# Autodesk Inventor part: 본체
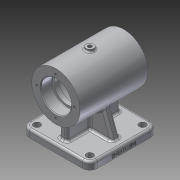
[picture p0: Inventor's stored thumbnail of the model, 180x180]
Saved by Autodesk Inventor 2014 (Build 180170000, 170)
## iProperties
Created: 2019-06
Part Number: 본체
Material: 알루미늄 6061
Document SubType Name: Modeling
Designer: OA55
Density: 2.71 g/cm^3
Appearance: 알루미늄 - 평지
Author: OA55
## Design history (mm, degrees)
sketch "스케치1"
  geometry: C1 r 32 at (0, 0); 1 further point
  constraints: 1 centre point, 1 coincident
  dimensions: "d0" = 64 diameter of C1
extrude "돌출1" new body sketch "스케치1" stored distance "d1" = 90; taper "d2" = 0 deg
node "작업 평면1"
sketch "스케치2"
  geometry: C1 r 25 at (0, 0); 1 further point
  constraints: 1 centre point, 1 coincident
  dimensions: "d3" = 50 diameter of C1
extrude "돌출2" cut sketch "스케치2" stored distance "d4" = 48; taper "d5" = 0 deg
sketch "스케치3"
  geometry: C1 r 32 at (0, 0) reference; C2 r 20 at (0, 0)
  constraints: 1 centre point, 1 coincident
  dimensions: "d6" = 40 diameter of C2
extrude "돌출3" cut sketch "스케치3" distance "d7" = 15; taper "d8" = 0 deg
node "작업 평면2"
sketch "스케치4"
  geometry: C1 r 20 at (0, 0) reference; C2 r 17 at (0, 0)
  constraints: 1 centre point, 1 coincident
  dimensions: "d9" = 34 diameter of C2
extrude "돌출4" cut sketch "스케치4" stored distance "d10" = 15; taper "d11" = 0 deg
sketch "스케치5" dims "d12" = 50
  geometry: L1 (0, 0)-(0, 25); C1 r 32 at (0, 0) reference; 1 further point
  constraints: 2 coincident, 2 end point, 1 vertical, 1 vertical alignment, 2 other
hole "구멍1" sketch "스케치5" at (0, 25) diameter "d13" = 3.242; stored, may be unused: countersink angle "d17" = 90 deg, drill point angle "d19" = 118 deg; dims "d14" = 7, "d15" = 4, "d16" = 2, "d18" = 9
node "작업 평면3"
node "작업 평면4"
sketch "스케치6"
  geometry: C1 r 5 at (0, 0); 1 further point
  constraints: 1 centre point, 1 coincident
  dimensions: "d24" = 10 diameter of C1
extrude "돌출5" join sketch "스케치6" stored distance "d25" = 10; taper "d26" = 0 deg
sketch "스케치7"
  geometry: 2 further points
  constraints: 1 coincident
hole "구멍2" sketch "스케치7" at (0, 0) diameter "d27" = 4.917; stored, may be unused: countersink angle "d31" = 90 deg, drill point angle "d33" = 118 deg; dims "d28" = 10, "d29" = 4, "d30" = 2, "d32" = 20
fillet "모깎기1" dims "d34" = 2
node "작업 평면6"
sketch "스케치8"
  geometry: L1 (0, 0)-(0, 45); L2 (0, 45)-(-45, 45); L3 (-45, 45)-(-45, -45); L4 (-45, -45)-(45, -45); L5 (45, -45)-(45, 45); L6 (45, 45)-(0, 45); 1 further point
  constraints: 12 end point, 3 vertical, 2 horizontal, 1 coincident
  dimensions: "d37" = 45 distance of L1.start L1.end; "d38" = 45 distance of L1.end L2.end; "d39" = 90 distance of L2.end L3.end; "d40" = 90 distance of L3.end L4.end; "d41" = 90 distance of L4.end L5.end
extrude "돌출6" join sketch "스케치8" distance "d42" = 10; taper "d43" = 0 deg
fillet "모깎기2" dims "d44" = 10
sketch "스케치9"
  geometry: C1 r 4.5 at (-35, 35); C2 r 4.5 at (35, 35); C3 r 4.5 at (-35, -35); C4 r 4.5 at (35, -35); A1 r 10 centre (-35, 35) between (-35, 45) and (-45, 35) reference; A2 r 10 centre (-35, -35) between (-45, -35) and (-35, -45) reference; A3 r 10 centre (35, -35) between (35, -45) and (45, -35) reference; A4 r 10 centre (35, 35) between (45, 35) and (35, 45) reference; 1 further point
  constraints: 4 centre point, 4 coincident
  dimensions: "d45" = 9 diameter of C1; "d46" = 9 diameter of C2; "d47" = 9 diameter of C3; "d48" = 9 diameter of C4
fillet "모깎기3" dims "d51" = 3
fillet "모깎기4" dims "d52" = 0.6
sketch "스케치11"
  geometry: L1 (35, -45)-(-35, -45) reference; L2 (45, 35)-(45, -35) reference; L3 (-35, 45)-(35, 45) reference; L4 (0, 0)-(0, 40); L5 (0, 40)-(-26.34, 40); L6 (-40, 26.34)-(-40, -26.34); L7 (-26.34, -40)-(26.34, -40); L8 (40, -26.34)-(40, 26.34); L9 (26.34, 40)-(0, 40); A1 r 10 centre (-35, -35) between (-45, -35) and (-35, -45) reference; A2 r 10 centre (35, -35) between (35, -45) and (45, -35) reference; A3 r 10 centre (35, 35) between (45, 35) and (35, 45) reference; A4 r 10 centre (-35, 35) between (-35, 45) and (-45, 35) reference; A5 r 10 centre (35, 35) between (26.34, 40) and (40, 26.34); A6 r 10 centre (35, -35) between (40, -26.34) and (26.34, -40); A7 r 10 centre (-35, -35) between (-26.34, -40) and (-40, -26.34); A8 r 10 centre (-35, 35) between (-40, 26.34) and (-26.34, 40)
  constraints: 16 end point, 8 point on circle, 4 centre point, 4 coincident, 3 vertical, 2 horizontal
  dimensions: "d53" = 40 distance of L4.start L4.end; "d62" = 10 radius of A8; "d63" = 10 radius of A5; "d66" = 52.67949 distance of L8.start L8.end; "d67" = 52.67949 distance of L7.start L7.end; "d68" = 52.67949 distance of L6.start L6.end; "d69" = 26.33975 distance of L9.start L4.end; "d70" = 10 radius of A6; "d71" = 10 radius of A7
extrude "돌출8" cut sketch "스케치11" distance "d72" = 5; taper "d73" = 0 deg
fillet "모깎기5" dims "d74" = 3
extrude "돌출9" cut sketch "스케치9" distance "d75" = 10; taper "d76" = 0 deg
fillet "모깎기6" dims "d77" = 3
sketch "스케치12"
  geometry: L1 (0, 0)-(0, -35); L2 (0, 0)-(0, 35); L3 (0, 35)-(5, 35); L4 (5, 35)-(5, -35); L5 (5, -35)-(-5, -35); L6 (-5, -35)-(-5, 35); L7 (-5, 35)-(0, 35)
  constraints: 14 end point, 4 vertical, 2 horizontal
  dimensions: "d78" = 35 distance of L1.start L1.end; "d79" = 35 distance of L1.start L2.end; "d80" = 5 distance of L2.end L3.end; "d81" = 70 distance of L3.end L4.end; "d82" = 10 distance of L4.end L5.end; "d83" = 70 distance of L5.end L6.end
extrude "돌출10" join sketch "스케치12" stored distance "d84" = 10; taper "d85" = 0 deg
node "작업 평면7"
sketch "스케치13"
  geometry: L1 (40, -65)-(40, -60) reference; L2 (40, -60)-(-40, -60) reference; L3 (-40, -60)-(-40, -65) reference; L4 (-40, -65)-(-45, -65) reference; L5 (-45, -65)-(-45, -58) reference; L6 (-42, -55)-(-5, -55) reference; L7 (-5, -55)-(-5, -31.607) reference; L8 (-5, 33.272)-(-5, 35) reference; L9 (-5, 35)-(-2.458, 35) reference; L10 (-2.458, 35)-(-2.458, 24.879) reference; L11 (2.458, 24.879)-(2.458, 35) reference; L12 (2.458, 35)-(5, 35) reference; L13 (5, 35)-(5, 33.272) reference; L14 (5, -31.607)-(5, -55) reference; L15 (5, -55)-(42, -55) reference; L16 (45, -58)-(45, -65) reference; L17 (45, -65)-(40, -65) reference; L18 (-35, -55)-(-23.058, -22.189); L19 (35, -55)-(23.058, -22.189); A1 r 3 centre (-42, -58) between (-42, -55) and (-45, -58) reference; A2 r 32 centre (0, 0) between (-6.588, 31.314) and (-5, -31.607) reference; A3 r 25 centre (0, 0) between (-2.458, 24.879) and (2.458, 24.879) reference; A4 r 32 centre (0, 0) between (5, -31.607) and (6.588, 31.314) reference; A5 r 3 centre (42, -58) between (45, -58) and (42, -55) reference; 1 further point
  constraints: 4 end point, 2 point on circle, 2 point on line, 2 other
  dimensions: "d87" = 10 distance from line of L18.start L5; "d88" = 10 distance from line of L16 L19.start; "d89" = 110 deg angle of L18 L6; "d90" = 110 deg angle of L15 L19
  node "절단 모서리 투영2"
feature "리브1" dims "d91" = 1, "d92" = 10, "d93" = 0, "d94" = 0, "d95" = 1, "d96" = 1
feature "리브2" dims "d97" = 1, "d98" = 10, "d99" = 0, "d100" = 0, "d101" = 1, "d102" = 1
fillet "모깎기7" dims "d103" = 3
fillet "모깎기8" dims "d104" = 3
fillet "모깎기9" dims "d105" = 3
sketch "스케치14"
  geometry: L1 (0, 0)-(70, 0) reference; L2 (-10, 7)-(-10, 0) reference; 2 further points
  constraints: 1 other
  dimensions: "d106" = 4 distance from line of L1 point (35, 4); "d107" = 45 distance from line of point (35, 4) L2
feature "엠보싱1" sketch "스케치14" dims "d108" = 0.5, "d109" = 0
chamfer "모따기1" distance "d110" = 1; stored, may be unused: second distance "d111" = 2, angle "d112" = 45 deg
node "솔리드1"
mirror "대칭1"
pattern_circular "원형 패턴1" dims angle "d21" = 360 deg
mirror "대칭2"
other parameters: "d23" = 35, "d36" = -65, "d86" = 0
